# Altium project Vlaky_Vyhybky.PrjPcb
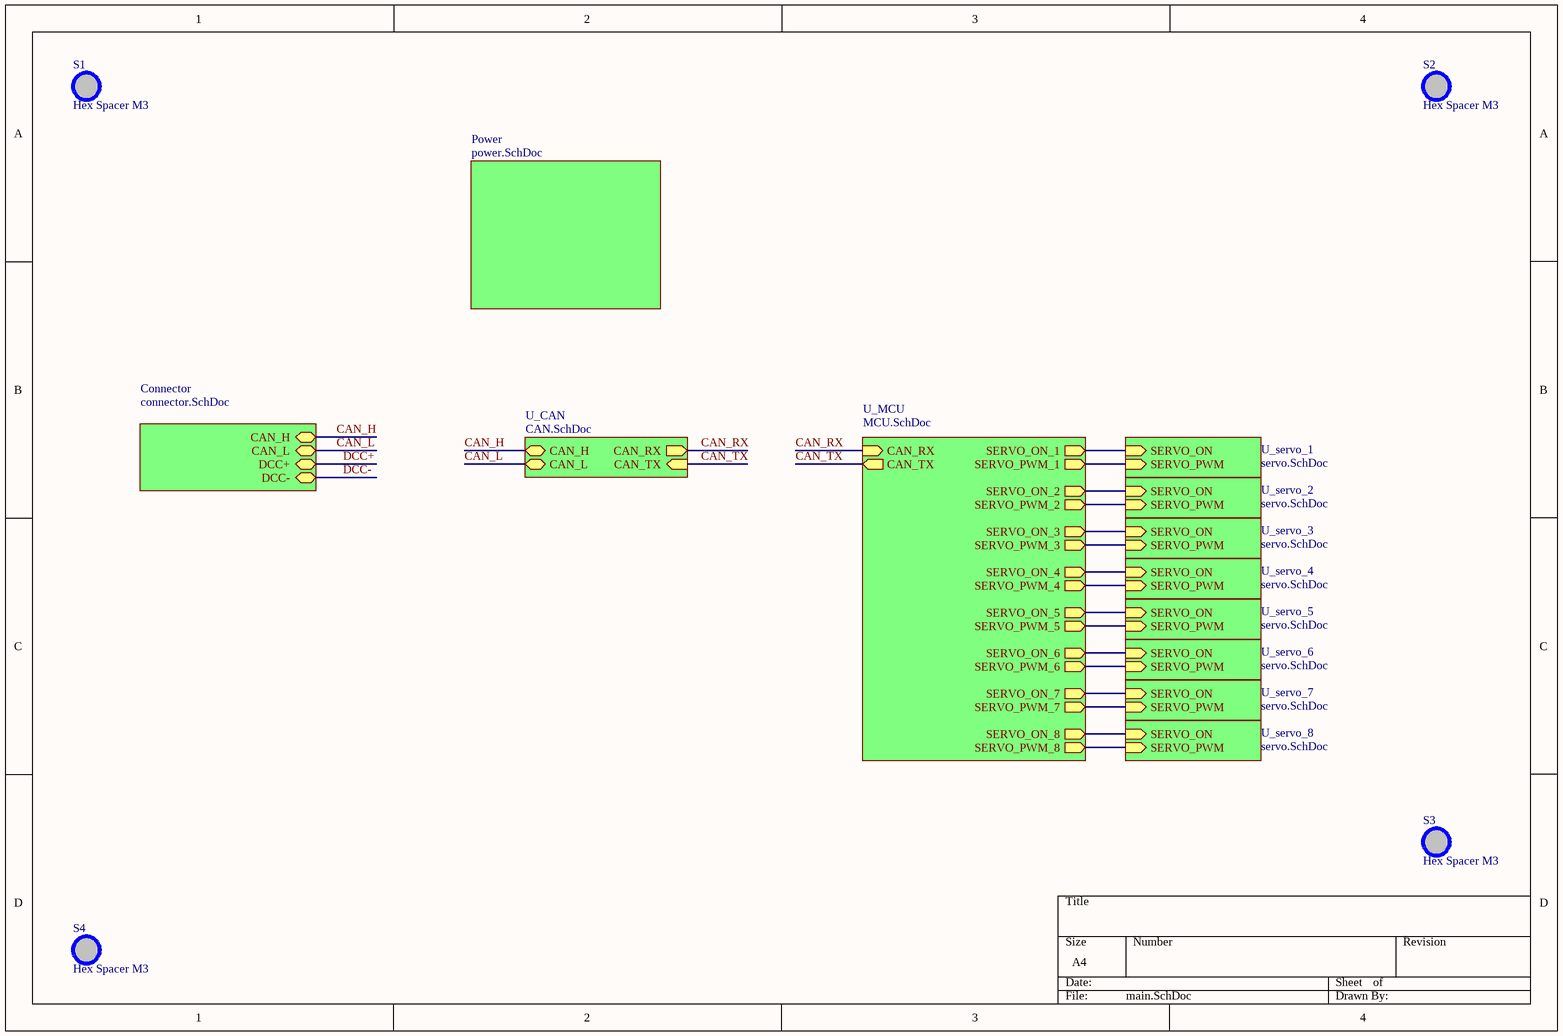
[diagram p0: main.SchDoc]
6 sheets, 83 parts. Net scope: hierarchical (ports join the sheet entries above them; power ports are global).
Board file: Vlaky_Vyhybky_v2019_02_26.PcbDoc
Sheets:
  main.SchDoc
    Connector = connector.SchDoc
    U_MCU = MCU.SchDoc
    U_CAN = CAN.SchDoc
    Power = power.SchDoc
    U_servo_1 = servo.SchDoc
    U_servo_2 = servo.SchDoc
    U_servo_3 = servo.SchDoc
    U_servo_4 = servo.SchDoc
    U_servo_5 = servo.SchDoc
    U_servo_6 = servo.SchDoc
    U_servo_7 = servo.SchDoc
    U_servo_8 = servo.SchDoc

## Sheet main.SchDoc
size A4

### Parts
S1  Hex Spacer M3  [THT_HEX_SPACER_M3L20]
S2  Hex Spacer M3  [THT_HEX_SPACER_M3L20]
S3  Hex Spacer M3  [THT_HEX_SPACER_M3L20]
S4  Hex Spacer M3  [THT_HEX_SPACER_M3L20]

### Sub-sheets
Connector = connector.SchDoc: CAN_H (bidir), CAN_L (bidir), DCC+ (bidir), DCC- (bidir)
Power = power.SchDoc: no entries
U_CAN = CAN.SchDoc: CAN_H (bidir), CAN_L (bidir), CAN_RX (out), CAN_TX (in)
U_MCU = MCU.SchDoc: CAN_RX (in), CAN_TX (out), SERVO_ON_1 (out), SERVO_PWM_1 (out), SERVO_PWM_2 (out), SERVO_ON_2 (out), SERVO_ON_3 (out), SERVO_ON_4 (out), SERVO_ON_5 (out), SERVO_ON_6 (out), SERVO_ON_7 (out), SERVO_ON_8 (out), SERVO_PWM_3 (out), SERVO_PWM_4 (out), SERVO_PWM_5 (out), SERVO_PWM_6 (out), SERVO_PWM_7 (out), SERVO_PWM_8 (out)
U_servo_1 = servo.SchDoc: SERVO_ON (in), SERVO_PWM (in)
U_servo_2 = servo.SchDoc: SERVO_ON (in), SERVO_PWM (in)
U_servo_3 = servo.SchDoc: SERVO_ON (in), SERVO_PWM (in)
U_servo_4 = servo.SchDoc: SERVO_ON (in), SERVO_PWM (in)
U_servo_5 = servo.SchDoc: SERVO_ON (in), SERVO_PWM (in)
U_servo_6 = servo.SchDoc: SERVO_ON (in), SERVO_PWM (in)
U_servo_7 = servo.SchDoc: SERVO_ON (in), SERVO_PWM (in)
U_servo_8 = servo.SchDoc: SERVO_ON (in), SERVO_PWM (in)

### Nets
CAN_H: sheet Connector/CAN_H, sheet U_CAN/CAN_H
CAN_L: sheet Connector/CAN_L, sheet U_CAN/CAN_L
CAN_RX: sheet U_MCU/CAN_RX, sheet U_CAN/CAN_RX
CAN_TX: sheet U_MCU/CAN_TX, sheet U_CAN/CAN_TX
NetLED4A_2: sheet U_MCU/SERVO_ON_1, sheet U_servo_1/SERVO_ON
NetLED4B_2: sheet U_MCU/SERVO_ON_2, sheet U_servo_2/SERVO_ON
NetLED4C_2: sheet U_MCU/SERVO_ON_3, sheet U_servo_3/SERVO_ON
NetLED4D_2: sheet U_MCU/SERVO_ON_4, sheet U_servo_4/SERVO_ON
NetLED4E_2: sheet U_MCU/SERVO_ON_5, sheet U_servo_5/SERVO_ON
NetLED4F_2: sheet U_MCU/SERVO_ON_6, sheet U_servo_6/SERVO_ON
NetLED4G_2: sheet U_MCU/SERVO_ON_7, sheet U_servo_7/SERVO_ON
NetLED4H_2: sheet U_MCU/SERVO_ON_8, sheet U_servo_8/SERVO_ON
NetP8A_1: sheet U_MCU/SERVO_PWM_1, sheet U_servo_1/SERVO_PWM
NetP8B_1: sheet U_MCU/SERVO_PWM_2, sheet U_servo_2/SERVO_PWM
NetP8C_1: sheet U_MCU/SERVO_PWM_3, sheet U_servo_3/SERVO_PWM
NetP8D_1: sheet U_MCU/SERVO_PWM_4, sheet U_servo_4/SERVO_PWM
NetP8E_1: sheet U_MCU/SERVO_PWM_5, sheet U_servo_5/SERVO_PWM
NetP8F_1: sheet U_MCU/SERVO_PWM_6, sheet U_servo_6/SERVO_PWM
NetP8G_1: sheet U_MCU/SERVO_PWM_7, sheet U_servo_7/SERVO_PWM
NetP8H_1: sheet U_MCU/SERVO_PWM_8, sheet U_servo_8/SERVO_PWM

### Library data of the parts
S1-S4 = HEX_SPACER_M3: Hexagon metal spacer M3

## Sheet connector.SchDoc
size A4
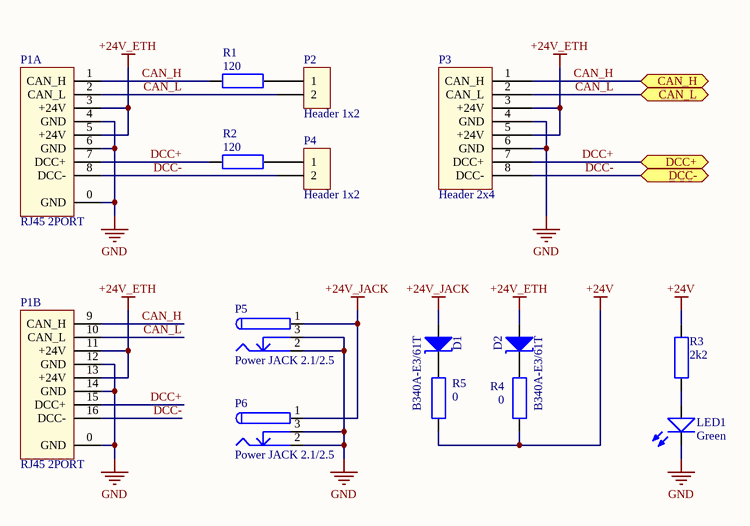
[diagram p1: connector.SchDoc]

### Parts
D1  B340A-E3/61T  [SMD_DO-214AC]
D2  B340A-E3/61T  [SMD_DO-214AC]
LED1  Green  [THT_LED_3MM]
P1  RJ45 2PORT  [THT_RJ45_2PORT]  (parts A,B of 2)
P2  Header 1x2  [THT_HEADER_100MIL_1X2_MALE]
P3  Header 2x4  [SMD_HEADER_100MIL_2X4_DOUBLESIDED]
P4  Header 1x2  [THT_HEADER_100MIL_1X2_MALE]
P5  Power JACK 2.1/2.5  [THT_POWER_JACK_2.1/2.5]
P6  Power JACK 2.1/2.5  [THT_POWER_JACK_2.1/2.5]
R1  120  [SMD_RESISTOR_0805]
R2  120  [SMD_RESISTOR_0805]
R3  2k2  [SMD_RESISTOR_0805]
R4  0  [SMD_RESISTOR_0805]
R5  0  [SMD_RESISTOR_0805]

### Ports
CAN_H (bidir), CAN_L (bidir), DCC+ (bidir), DCC- (bidir)

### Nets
+24V: R3.2 R4.1 R5.1
+24V_ETH: D2.1 P1.3(+24V) P1.5(+24V) P1.11(+24V) P1.13(+24V) P3.3(+24V) P3.5(+24V)
+24V_JACK: D1.1 P5.1 P6.1
GND: LED1.2 P1.0(GND) P1.4(GND) P1.6(GND) P1.12(GND) P1.14(GND) P3.4(GND) P3.6(GND) P5.2 P5.3 P6.2 P6.3
CAN_H: P1.1(CAN_H) P1.9(CAN_H) P3.1(CAN_H) R1.2 ; port CAN_H
CAN_L: P1.2(CAN_L) P1.10(CAN_L) P2.2 P3.2(CAN_L) ; port CAN_L
DCC+: P1.7(DCC+) P1.15(DCC+) P3.7(DCC+) R2.2 ; port DCC+
DCC-: P1.8(DCC-) P1.16(DCC-) P3.8(DCC-) P4.2 ; port DCC-
NetD1_2: D1.2 R5.2
NetD2_2: D2.2 R4.2
NetLED1_1: LED1.1 R3.1
NetP2_1: P2.1 R1.1
NetP4_1: P4.1 R2.1

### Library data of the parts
D1 D2 = Diode_Schottky: Diode Schottky
LED1 = LED
P1 = RJ45_2PORT: RJ45 - 2 port; Objednací kód: RJHSE538002; Dodavatel: TME; Výrobce: AMPHENOL
P2 P4 = Header_1x2
P3 = Header_2x4_Trains_Project
P5 P6 = Power_JACK_2.1/2.5: Low Voltage Power Supply Connector
R1-R5 = Resistor

## Sheet MCU.SchDoc
size A4
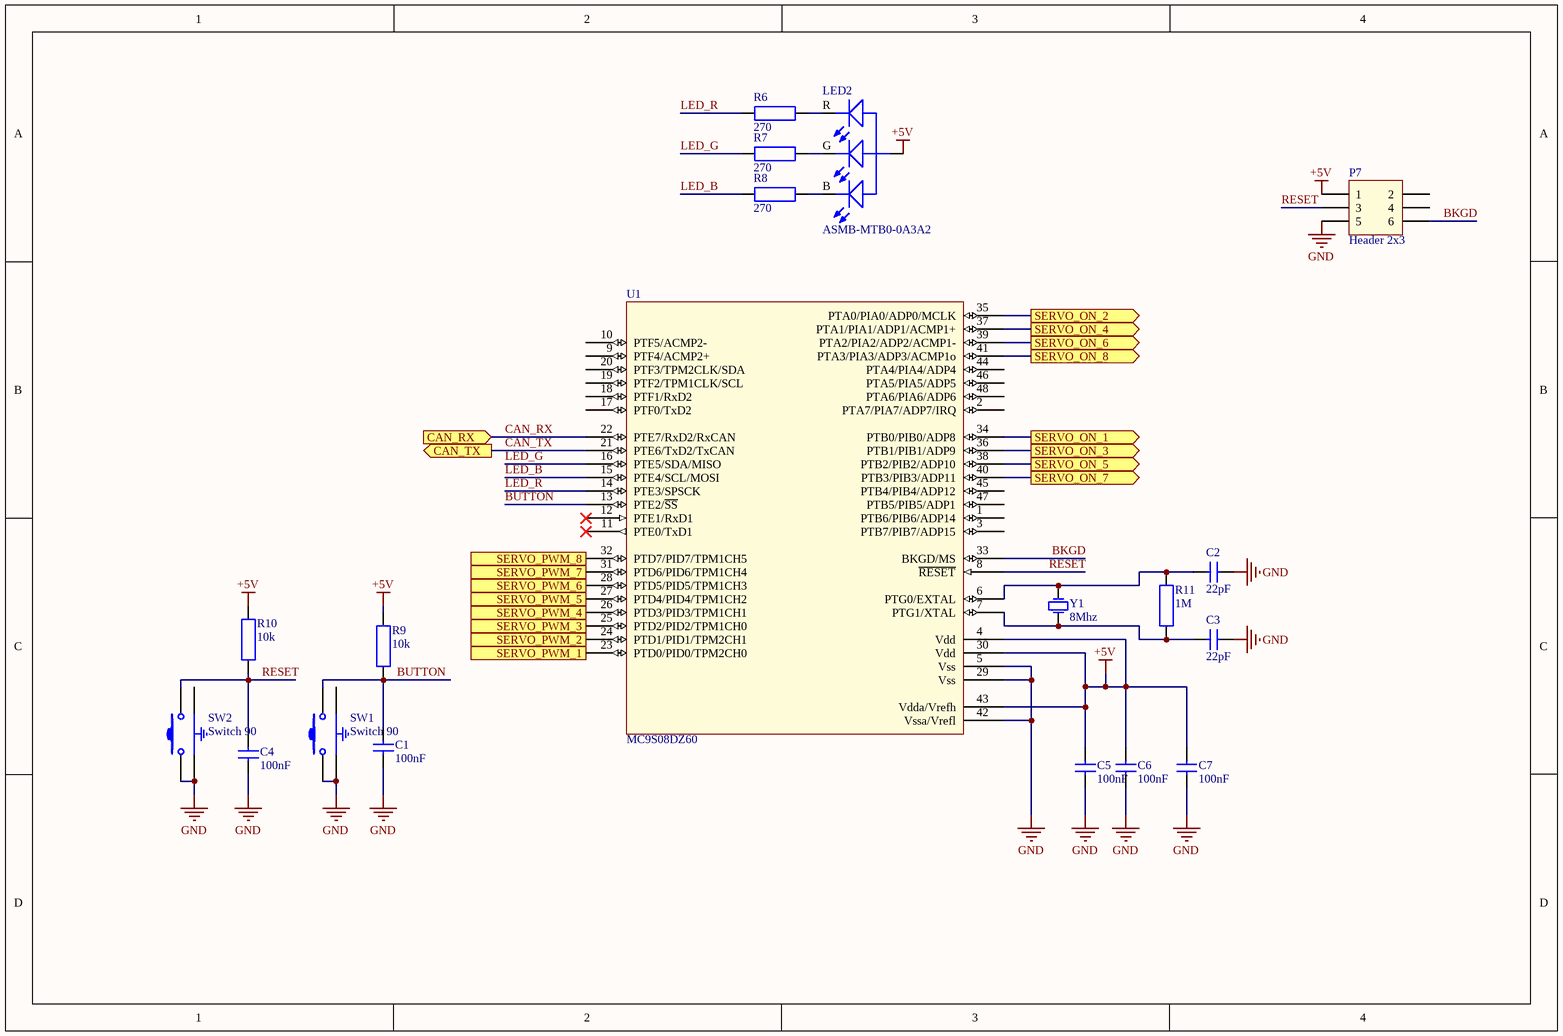
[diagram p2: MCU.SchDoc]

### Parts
C1  100nF  [SMD_CAPACITOR_0805]
C2  22pF  [SMD_CAPACITOR_0805]
C3  22pF  [SMD_CAPACITOR_0805]
C4  100nF  [SMD_CAPACITOR_0805]
C5  100nF  [SMD_CAPACITOR_0805]
C6  100nF  [SMD_CAPACITOR_0805]
C7  100nF  [SMD_CAPACITOR_0805]
LED2  ASMB-MTB0-0A3A2  [SMD_LED_RGB]
P7  Header 2x3  [THT_HEADER_100MIL_2X3_MALE]
R6  270  [SMD_RESISTOR_0805]
R7  270  [SMD_RESISTOR_0805]
R8  270  [SMD_RESISTOR_0805]
R9  10k  [SMD_RESISTOR_0805]
R10  10k  [SMD_RESISTOR_0805]
R11  1M  [SMD_RESISTOR_0805]
SW1  Switch 90  [THT_SWITCH_SPST_90]
SW2  Switch 90  [THT_SWITCH_SPST_90]
U1  MC9S08DZ60  [SMD_LQFP-48]
Y1  8Mhz  [SMD_XTAL_HC-49]

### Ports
CAN_RX (in), CAN_TX (out), SERVO_ON_1 (out), SERVO_ON_2 (out), SERVO_ON_3 (out), SERVO_ON_4 (out), SERVO_ON_5 (out), SERVO_ON_6 (out), SERVO_ON_7 (out), SERVO_ON_8 (out), SERVO_PWM_1 (out), SERVO_PWM_2 (out), SERVO_PWM_3 (out), SERVO_PWM_4 (out), SERVO_PWM_5 (out), SERVO_PWM_6 (out), SERVO_PWM_7 (out), SERVO_PWM_8 (out)

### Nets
+5V: C5.2 C6.2 C7.2 LED2.1(ANODE) P7.1 R9.2 R10.2 U1.4(Vdd) U1.30(Vdd) U1.43(Vdda/Vrefh)
GND: C1.1 C2.2 C3.2 C4.1 C5.1 C6.1 C7.1 P7.5 SW1.1 SW1.3 SW2.1 SW2.3 U1.5(Vss) U1.29(Vss) U1.42(Vssa/Vrefl)
BKGD: P7.6 U1.33(BKGD/MS)
BUTTON: C1.2 R9.1 SW1.2 U1.13(PTE2/~{SS})
CAN_RX: U1.22(PTE7/RxD2/RxCAN) ; port CAN_RX
CAN_TX: U1.21(PTE6/TxD2/TxCAN) ; port CAN_TX
LED_B: R8.1 U1.15(PTE4/SCL/MOSI)
LED_G: R7.1 U1.16(PTE5/SDA/MISO)
LED_R: R6.1 U1.14(PTE3/SPSCK)
RESET: C4.2 P7.3 R10.1 SW2.2 U1.8(~{RESET})
NetC2_1: C2.1 R11.2 U1.6(PTG0/EXTAL) Y1.2
NetC3_1: C3.1 R11.1 U1.7(PTG1/XTAL) Y1.1
NetLED2_2: LED2.2(B) R8.2
NetLED2_3: LED2.3(G) R7.2
NetLED2_4: LED2.4(R) R6.2
NetLED4A_2: U1.34(PTB0/PIB0/ADP8) ; port SERVO_ON_1
NetLED4B_2: U1.35(PTA0/PIA0/ADP0/MCLK) ; port SERVO_ON_2
NetLED4C_2: U1.36(PTB1/PIB1/ADP9) ; port SERVO_ON_3
NetLED4D_2: U1.37(PTA1/PIA1/ADP1/ACMP1+) ; port SERVO_ON_4
NetLED4E_2: U1.38(PTB2/PIB2/ADP10) ; port SERVO_ON_5
NetLED4F_2: U1.39(PTA2/PIA2/ADP2/ACMP1-) ; port SERVO_ON_6
NetLED4G_2: U1.40(PTB3/PIB3/ADP11) ; port SERVO_ON_7
NetLED4H_2: U1.41(PTA3/PIA3/ADP3/ACMP1o) ; port SERVO_ON_8
NetP8A_1: U1.23(PTD0/PID0/TPM2CH0) ; port SERVO_PWM_1
NetP8B_1: U1.24(PTD1/PID1/TPM2CH1) ; port SERVO_PWM_2
NetP8C_1: U1.25(PTD2/PID2/TPM1CH0) ; port SERVO_PWM_3
NetP8D_1: U1.26(PTD3/PID3/TPM1CH1) ; port SERVO_PWM_4
NetP8E_1: U1.27(PTD4/PID4/TPM1CH2) ; port SERVO_PWM_5
NetP8F_1: U1.28(PTD5/PID5/TPM1CH3) ; port SERVO_PWM_6
NetP8G_1: U1.31(PTD6/PID6/TPM1CH4) ; port SERVO_PWM_7
NetP8H_1: U1.32(PTD7/PID7/TPM1CH5) ; port SERVO_PWM_8

Not connected (* = marked no-connect by the designer): P7 2 4; SW1 4; SW2 4; U1 1(PTB6/PIB6/ADP14) 2(PTA7/PIA7/ADP7/IRQ) 3(PTB7/PIB7/ADP15) 9(PTF4/ACMP2+) 10(PTF5/ACMP2-) 11(PTE0/TxD1)* 12(PTE1/RxD1)* 17(PTF0/TxD2) 18(PTF1/RxD2) 19(PTF2/TPM1CLK/SCL) 20(PTF3/TPM2CLK/SDA) 44(PTA4/PIA4/ADP4) 45(PTB4/PIB4/ADP12) 46(PTA5/PIA5/ADP5) 47(PTB5/PIB5/ADP1) 48(PTA6/PIA6/ADP6)

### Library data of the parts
C1-C7 = Capacitor
LED2 = LED_RGB: LED RGB
P7 = Header_2x3
R6-R11 = Resistor
SW1 SW2 = Switch_90: Tactile Switch Right Angle
U1 = MC9S08DZ96: NXP 8 Bit Microcontroller, CAN
Y1 = XTAL: Crystal Oscillator

## Sheet CAN.SchDoc
size A4
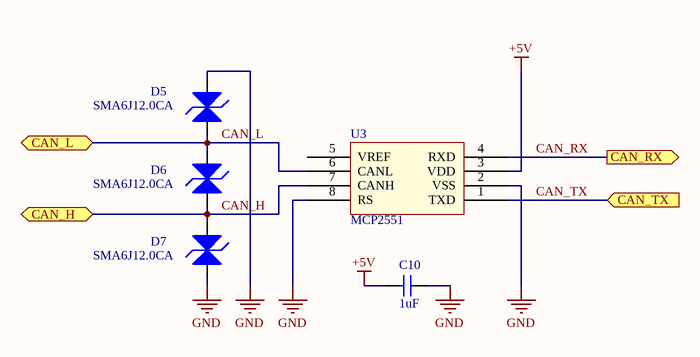
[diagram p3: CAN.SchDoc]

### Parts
C10  1uF  [SMD_CAPACITOR_0805]
D5  SMA6J12.0CA  [SMD_DO-214AC]
D6  SMA6J12.0CA  [SMD_DO-214AC]
D7  SMA6J12.0CA  [SMD_DO-214AC]
U3  MCP2551  [SMD_SOIC-8]

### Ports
CAN_H (bidir), CAN_L (bidir), CAN_RX (out), CAN_TX (in)

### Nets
+5V: C10.1 U3.3(VDD)
GND: C10.2 D5.2 D7.1 U3.2(VSS) U3.8(RS)
CAN_H: D6.1 D7.2 U3.7(CANH) ; port CAN_H
CAN_L: D5.1 D6.2 U3.6(CANL) ; port CAN_L
CAN_RX: U3.4(RXD) ; port CAN_RX
CAN_TX: U3.1(TXD) ; port CAN_TX

Not connected (* = marked no-connect by the designer): U3 5(VREF)

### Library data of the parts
C10 = Capacitor
D5-D7 = Transil: Transient Voltage Suppressor, Bidirectional
U3 = MCP2551: CAN Transceiver, 4.5 V - 5.5 V, 1 Mb/s

## Sheet power.SchDoc
size A4
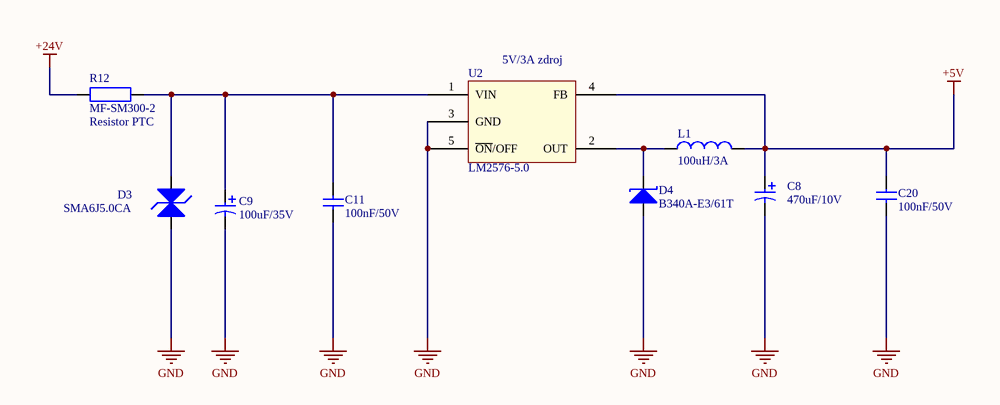
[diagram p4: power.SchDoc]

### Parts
C8  470uF/10V  [SMD_CAPACITOR_E_8MM]
C9  100uF/35V  [SMD_CAPACITOR_D_6.3MM]
C11  100nF/50V  [SMD_CAPACITOR_0805]
C20  100nF/50V  [SMD_CAPACITOR_0805]
D3  SMA6J5.0CA  [SMD_DO-214AC]
D4  B340A-E3/61T  [SMD_DO-214AC]
L1  100uH/3A  [SMD_INDUCTOR_12.5MM]
R12  MF-SM300-2  [SMD_RESISTOR_PTC_MF-SM]
U2  LM2576-5.0  [SMD_TO-263-5]

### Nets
+5V: C8.1 C20.2 L1.2 U2.4(FB)
+24V: R12.1
GND: C8.2 C9.2 C11.1 C20.1 D3.1 D4.1 U2.3(GND) U2.5(~{ON}/OFF)
NetC9_1: C9.1 C11.2 D3.2 R12.2 U2.1(VIN)
NetD4_2: D4.2 L1.1 U2.2(OUT)

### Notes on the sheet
- (near U2) 5V/3A zdroj

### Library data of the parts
C8 C9 = Capacitor_POL
C11 C20 = Capacitor
D3 = Transil: as D5 on sheet CAN
D4 = Diode_Schottky: Diode Schottky
L1 = Inductor
R12 = Resistor_PTC: Resistor PTC
U2 = LM2576-5.0: Step Down Switching Regulator, Fixed, 4V-40V Input, 5V and 3A Output

## Sheet servo.SchDoc
size A4
Used 8 times, as channels U_servo_1, U_servo_2, U_servo_3, U_servo_4, U_servo_5, U_servo_6, U_servo_7, U_servo_8. Parts and nets are listed once, with the designators drawn on the sheet.
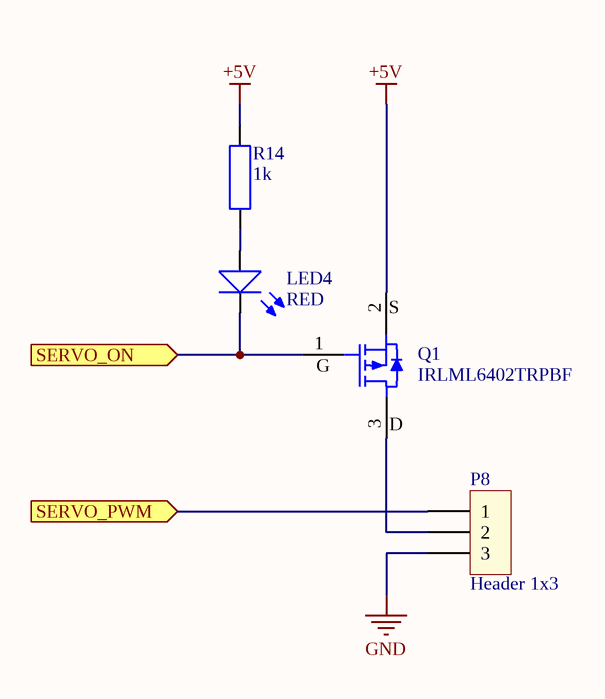
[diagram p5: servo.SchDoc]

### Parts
LED4  RED  [SMD_LED_1206]
P8  Header 1x3  [THT_HEADER_100MIL_1X3_MALE_90]
Q1  IRLML6402TRPBF  [SMD_SOT-23]
R14  1k  [SMD_RESISTOR_0805]

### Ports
SERVO_ON (in), SERVO_PWM (in)

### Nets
+5V: Q1.2 R14.2
GND: P8.3
SERVO_ON: LED4.2 Q1.1 ; port SERVO_ON
SERVO_PWM: P8.1 ; port SERVO_PWM
NetLED4_1: LED4.1 R14.1
NetP8_2: P8.2 Q1.3

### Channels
U_servo_1: designators end in A; ports SERVO_ON=NetLED4A_2 SERVO_PWM=NetP8A_1
U_servo_2: designators end in B; ports SERVO_ON=NetLED4B_2 SERVO_PWM=NetP8B_1
U_servo_3: designators end in C; ports SERVO_ON=NetLED4C_2 SERVO_PWM=NetP8C_1
U_servo_4: designators end in D; ports SERVO_ON=NetLED4D_2 SERVO_PWM=NetP8D_1
U_servo_5: designators end in E; ports SERVO_ON=NetLED4E_2 SERVO_PWM=NetP8E_1
U_servo_6: designators end in F; ports SERVO_ON=NetLED4F_2 SERVO_PWM=NetP8F_1
U_servo_7: designators end in G; ports SERVO_ON=NetLED4G_2 SERVO_PWM=NetP8G_1
U_servo_8: designators end in H; ports SERVO_ON=NetLED4H_2 SERVO_PWM=NetP8H_1

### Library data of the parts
LED4 = LED
P8 = Header_1x3
Q1 = Transistor_MOSFET_P: Transistor MOSFET P
R14 = Resistor

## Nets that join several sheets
+5V: MCU (10 pins), CAN (C10.1 U3.3), power (C8.1 C20.2 L1.2 U2.4), U_servo_1 (Q1A.2 R14A.2), U_servo_2 (Q1B.2 R14B.2), U_servo_3 (Q1C.2 R14C.2), U_servo_4 (Q1D.2 R14D.2), U_servo_5 (Q1E.2 R14E.2), U_servo_6 (Q1F.2 R14F.2), U_servo_7 (Q1G.2 R14G.2), U_servo_8 (Q1H.2 R14H.2)
+24V: connector (R3.2 R4.1 R5.1), power (R12.1)
GND: connector (12 pins), MCU (15 pins), CAN (5 pins), power (8 pins), U_servo_1 (P8A.3), U_servo_2 (P8B.3), U_servo_3 (P8C.3), U_servo_4 (P8D.3), U_servo_5 (P8E.3), U_servo_6 (P8F.3), U_servo_7 (P8G.3), U_servo_8 (P8H.3)
CAN_H: connector (P1.1 P1.9 P3.1 R1.2), CAN (D6.1 D7.2 U3.7)
CAN_L: connector (P1.2 P1.10 P2.2 P3.2), CAN (D5.1 D6.2 U3.6)
CAN_RX: MCU (U1.22), CAN (U3.4)
CAN_TX: MCU (U1.21), CAN (U3.1)
NetLED4A_2: MCU (U1.34), U_servo_1 (LED4A.2 Q1A.1)
NetLED4B_2: MCU (U1.35), U_servo_2 (LED4B.2 Q1B.1)
NetLED4C_2: MCU (U1.36), U_servo_3 (LED4C.2 Q1C.1)
NetLED4D_2: MCU (U1.37), U_servo_4 (LED4D.2 Q1D.1)
NetLED4E_2: MCU (U1.38), U_servo_5 (LED4E.2 Q1E.1)
NetLED4F_2: MCU (U1.39), U_servo_6 (LED4F.2 Q1F.1)
NetLED4G_2: MCU (U1.40), U_servo_7 (LED4G.2 Q1G.1)
NetLED4H_2: MCU (U1.41), U_servo_8 (LED4H.2 Q1H.1)
NetP8A_1: MCU (U1.23), U_servo_1 (P8A.1)
NetP8B_1: MCU (U1.24), U_servo_2 (P8B.1)
NetP8C_1: MCU (U1.25), U_servo_3 (P8C.1)
NetP8D_1: MCU (U1.26), U_servo_4 (P8D.1)
NetP8E_1: MCU (U1.27), U_servo_5 (P8E.1)
NetP8F_1: MCU (U1.28), U_servo_6 (P8F.1)
NetP8G_1: MCU (U1.31), U_servo_7 (P8G.1)
NetP8H_1: MCU (U1.32), U_servo_8 (P8H.1)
